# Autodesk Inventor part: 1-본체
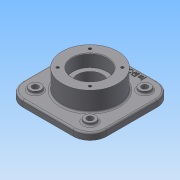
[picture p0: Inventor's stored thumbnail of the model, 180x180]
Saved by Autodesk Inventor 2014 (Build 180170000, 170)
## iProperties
Created: 2015-09
Part Number: 1-본체
Material: Generic
Document SubType Name: Modeling
Designer: study
Density: 1 g/cm^3
Appearance: Default
Author: study
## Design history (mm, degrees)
sketch "스케치1"
  geometry: L1 (-75, -75)-(75, -75); L2 (75, -75)-(75, 75); L3 (75, 75)-(-75, 75); L4 (-75, 75)-(-75, -75); L5 (-75, -75)-(75, 75); L6 (75, -75)-(-75, 75); 1 further point
  constraints: 12 end point, 2 midpoint, 2 parallel, 1 horizontal, 1 perpendicular
  dimensions: "d0" = 150 distance of L2.end L3.end; "d1" = 150 distance of L1.end L2.end
extrude "돌출1" new body sketch "스케치1" distance "d2" = 12; taper "d3" = 0 deg
fillet "모깎기1" dims "d4" = 30
node "작업 평면1"
sketch "스케치2"
  geometry: C1 r 50 at (0, 0); 1 further point
  constraints: 1 centre point, 1 coincident
  dimensions: "d6" = 100 diameter of C1
extrude "돌출2" join sketch "스케치2" distance "d7" = 70; taper "d8" = 0 deg
sketch "스케치7"
  geometry: L1 (-49, -49)-(49, -49); L2 (49, -49)-(49, 49); L3 (49, 49)-(-49, 49); L4 (-49, 49)-(-49, -49); L5 (-49, -49)-(49, 49); L6 (49, -49)-(-49, 49); C1 r 50 at (0, 0) reference; C2 r 10 at (-49, 49); C3 r 10 at (49, 49); C4 r 10 at (-49, -49); C5 r 10 at (49, -49)
  constraints: 12 end point, 4 centre point, 4 coincident, 3 equal radius, 2 midpoint, 2 parallel, 1 horizontal, 1 perpendicular
  dimensions: "d58" = 98 distance of L2.end L3.end; "d59" = 98 distance of L1.end L2.end; "d60" = 20 diameter of C2
extrude "돌출4" join sketch "스케치7" distance "d61" = 5; taper "d62" = 0 deg
sketch "스케치4"
  geometry: C1 r 50 at (0, 0) reference; C2 r 50 at (0, 0) reference; 1 further point
  constraints: 1 vertical alignment, 1 other
  dimensions: "d12" = 65 distance of C1.centre point (0, 65)
feature "엠보싱1" sketch "스케치4" dims "d0" = 150, "d1" = 150, "d13" = 1, "d14" = 0
sketch "스케치8"
  geometry: C1 r 10 at (0, 0) reference; C2 r 10 at (0, -98) reference; C3 r 10 at (98, -98) reference; C4 r 10 at (98, 0) reference; 5 further points
  constraints: 4 coincident
hole "구멍5" sketch "스케치8" at (0, 0), (0, -98), (98, -98), (98, 0) diameter "d63" = 11; stored, may be unused: countersink angle "d67" = 90 deg, drill point angle "d69" = 0 deg; dims "d64" = 10, "d65" = 62, "d66" = 22, "d68" = 17
hole "구멍2" diameter "d24" = 45; stored, may be unused: countersink angle "d28" = 90 deg, drill point angle "d30" = 0 deg; dims "d22" = 10, "d23" = 10, "d25" = 6, "d26" = 62, "d27" = 22, "d29" = 48
hole "구멍3" diameter "d33" = 45; stored, may be unused: countersink angle "d37" = 90 deg, drill point angle "d39" = 0 deg; dims "d31" = 10, "d32" = 10, "d34" = 6, "d35" = 62, "d36" = 22, "d38" = 48
sketch "스케치6"
  geometry: L1 (0, 0)-(41, 0); C1 r 31 at (0, 0) reference; C2 r 50 at (0, 0) reference; A1 r 41 centre (0, 0) between (-28.991, 28.991) and (28.991, 28.991); 2 further points
  constraints: 5 point on circle, 2 end point, 2 horizontal alignment, 1 centre point, 1 coincident, 1 horizontal, 1 vertical alignment
  dimensions: "d40" = 82 diameter of A1; "d41" = 45 deg dimension on C1.centre L1.end A1.end
hole "구멍4" sketch "스케치6" at (-28.991, 28.991), (28.991, 28.991), (-28.991, -28.991), (28.991, -28.991) diameter "d42" = 4.917; stored, may be unused: countersink angle "d46" = 90 deg, drill point angle "d48" = 118 deg; dims "d43" = 10, "d44" = 62, "d45" = 22, "d47" = 13
node "작업 평면2"
chamfer "모따기1" distance "d50" = 1; stored, may be unused: second distance "d51" = 2, angle "d52" = 45 deg
fillet "모깎기2" dims "d53" = 0.3
fillet "모깎기4" dims "d70" = 3
node "솔리드1"
mirror "대칭1"
node "투영된 루프3"
node "투영된 루프4"
node "투영된 루프5"
other parameters: "d5" = -23, "d49" = 12
